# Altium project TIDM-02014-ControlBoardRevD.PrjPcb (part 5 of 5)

## Sheet LDC.SchDoc: Resolver Analog Front-End
size 431 x 279 mm; Date: Not shown in title block; ApprovedBy: Not shown in title block; CheckedBy: Not shown in title block; Author: Not shown in title block; CompanyName: Not shown in title block; DrawnBy: Panacek; Engineer: Not shown in title block; Organization: Not shown in title block; Address1: Not shown in title block; Address2: Not shown in title block; Address3: Not shown in title block; Address4: Not shown in title block; DocumentNumber: 19; Revision: Use project parameter SCH_Rev; SheetNumber: 19; SheetTotal: 19; PageSetup: Record=PageOptions¦CenterHorizontal=True¦CenterVertical=True¦PrintScale=1.00¦XCorrection=1.00¦YCorrection=1.00¦PrintKind=0¦BorderSize=5000000¦LeftOffset=0¦BottomOffset=0¦Orientation=2¦PaperLength=1000¦PaperWidth=1000¦Scale=100¦PaperSource=15¦PrintQuality=600¦MediaType=1¦DitherType=10¦PaperKind=Letter¦PrintScaleMode=1
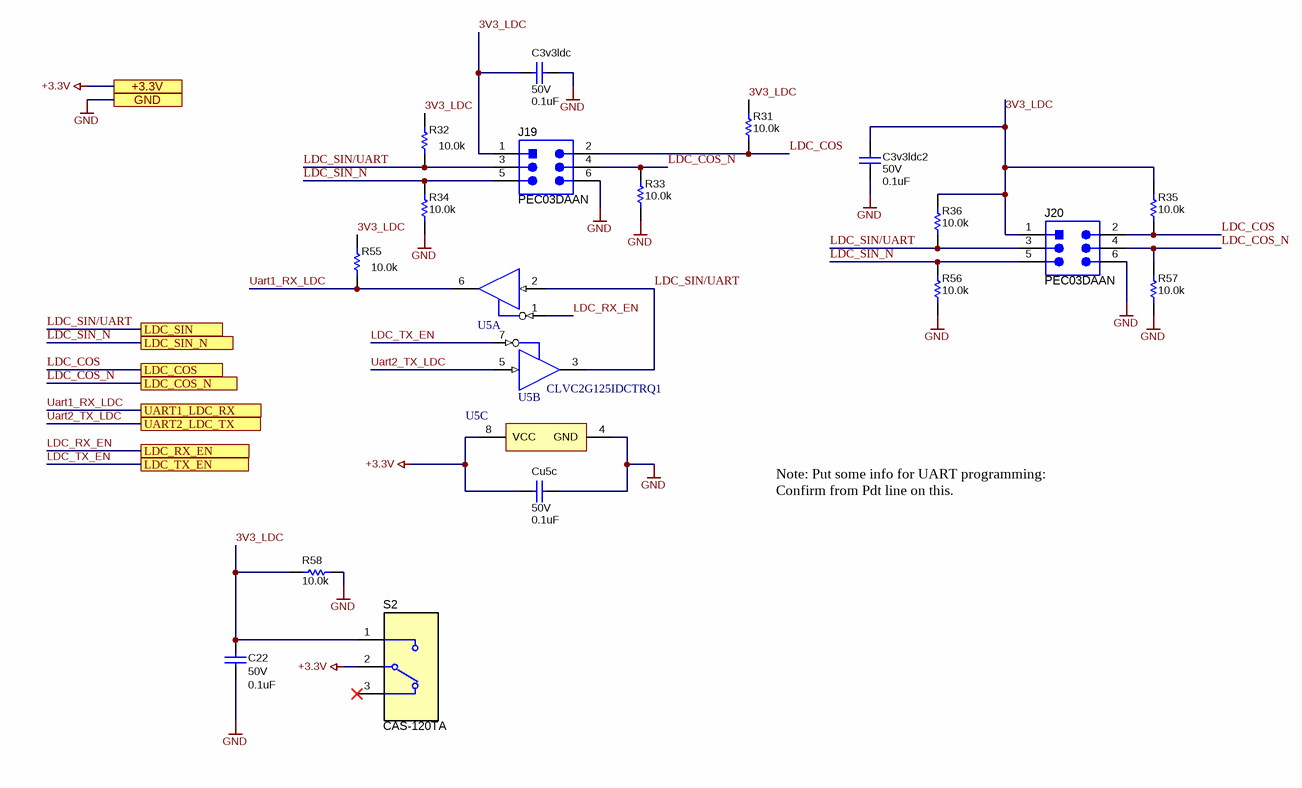
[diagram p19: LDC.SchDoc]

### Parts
C3v3ldc  VDC_V: 50V  ValueDisplayed: 0.1uF  [0603]  (hidden comment: CGA3E2X7R1H104K080AA)
C3v3ldc2  VDC_V: 50V  ValueDisplayed: 0.1uF  [0603]  (hidden comment: CGA3E2X7R1H104K080AA)
C22  VDC_V: 50V  ValueDisplayed: 0.1uF  [0603]  (hidden comment: CGA3E2X7R1H104K080AA)
Cu5c  VDC_V: 50V  ValueDisplayed: 0.1uF  [0603]  (hidden comment: CGA3E2X7R1H104K080AA)
J19  PEC03DAAN  [SULLINS_PEC03DAAN]
J20  PEC03DAAN  [SULLINS_PEC03DAAN]
R31  ValueDisplayed: 10.0k  [0603]  (hidden comment: CRCW060310K0FKEA)
R32  ValueDisplayed: 10.0k  [0603]  (hidden comment: CRCW060310K0FKEA)
R33  ValueDisplayed: 10.0k  [0603]  (hidden comment: CRCW060310K0FKEA)
R34  ValueDisplayed: 10.0k  [0603]  (hidden comment: CRCW060310K0FKEA)
R35  ValueDisplayed: 10.0k  [0603]  (hidden comment: CRCW060310K0FKEA)
R36  ValueDisplayed: 10.0k  [0603]  (hidden comment: CRCW060310K0FKEA)
R55  ValueDisplayed: 10.0k  [0603]  (hidden comment: CRCW060310K0FKEA)
R56  ValueDisplayed: 10.0k  [0603]  (hidden comment: CRCW060310K0FKEA)
R57  ValueDisplayed: 10.0k  [0603]  (hidden comment: CRCW060310K0FKEA)
R58  ValueDisplayed: 10.0k  [0603]  (hidden comment: CRCW060310K0FKEA)
S2  CAS-120TA  [SW_CAS-120TA]
U5  CLVC2G125IDCTRQ1  [DCT0008A_N]  (value not drawn)  (parts A,B,C of 3)

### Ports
+3.3V, GND, LDC_COS, LDC_COS_N, LDC_RX_EN, LDC_SIN, LDC_SIN_N, LDC_TX_EN, UART1_LDC_RX, UART2_LDC_TX

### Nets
+3.3V: Cu5c.1 S2.2 U5.8(VCC) ; port +3.3V
GND: C3v3ldc.2 C3v3ldc2.2 C22.2 Cu5c.2 J19.6 J20.6 R33.1 R34.1 R56.1 R57.1 R58.1 U5.4(GND) ; port GND
3V3_LDC: C3v3ldc.1 C3v3ldc2.1 C22.1 J19.1 J20.1 R31.2 R32.2 R35.2 R36.2 R55.2 R58.2 S2.1  [project net 3V3_LDC_19]
LDC_COS: J19.2 J20.2 R31.1 R35.1 ; port LDC_COS
LDC_COS_N: J19.4 J20.4 R33.2 R57.2 ; port LDC_COS_N
LDC_RX_EN: U5.1(1~{OE}) ; port LDC_RX_EN
LDC_SIN/UART: J19.3 J20.3 R32.1 R36.1 U5.2(1A) U5.3(2Y) ; port LDC_SIN  [project net LDC_SIN]
LDC_SIN_N: J19.5 J20.5 R34.2 R56.2 ; port LDC_SIN_N
LDC_TX_EN: U5.7(2~{OE}) ; port LDC_TX_EN
Uart1_RX_LDC: R55.1 U5.6(1Y) ; port UART1_LDC_RX  [project net UART1_LDC_RX]
Uart2_TX_LDC: U5.5(2A) ; port UART2_LDC_TX  [project net UART2_LDC_TX]

Not connected (* = marked no-connect by the designer): S2 3*

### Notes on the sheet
- Note: Put some info for UART programming: Confirm from Pdt line on this.

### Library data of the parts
C3v3ldc C3v3ldc2 C22 Cu5c = CMP-0007078-4: CAP, CERM, 0.1 uF, 50 V, +/- 10%, X7R, AEC-Q200 Grade 1, 0603; Manufacturer: TDK; TaMin_C: -55°C; ESR_ohm: 29.6m; Polarized: N; SizeAreaWB_mm2: 4.68; Value1: 0.0296 ohm; U/M: EA; Value: 0.1uF; TaMax_C: 125°C; SizeZ_mm: 1; SizeX_mm: 1.6; SizeY_mm: 0.8; SizeArea_mm2: 1.28; AEC Qualified: Y; Cap_F: 100nF; IRMS_A: 971.99mA; AEC Category: Q200
J19 J20 = CMP-0054552-2: Header, 100mil, 3x2, Tin, TH; Manufacturer: Sullins Connector Solutions; Current_A: 3A; Green_Lifecycle: Not Set; Shrouded: N; Gender: Male; Green_REACh: Incomplete; Voltage_V: 1.8kV; Row_Count: 2; RowSpacing_mm: 2.54; Cert_UL: Y
R31-R36 R55-R58 = CMP-0021998-4: RES, 10.0 k, 1%, 0.1 W, AEC-Q200 Grade 0, 0603; Manufacturer: Vishay-Dale; Power_W: 100mW; TempCo: 100 ppm/C; Value_Code: 10k0; Value: 10.0k; EIA_Code: E96; Res_ohm: 10k; SizeX_mm: 1.6; SizeY_mm: 0.8; SizeZ_mm: 1; Value2: 0.1W; SizeArea_mm2: 1.28; AEC Qualified: Y; VDC_V: 75V; AEC Category: Q200; AEC Grade: 0
S2 = CMP-0002139-2: Switch, Slide, SPDT  100mA, SMT; Manufacturer: Copal Electronics; CurrentRating_mA: 100A; SwitchFunction: On-On; VDC_V: 6V; PositionCount: 1
U5 = CMP-0051817-1: Automotive Catalog Dual Bus Buffer Gate with 3-State Outputs, DCT0008A, LARGE T&R; Generic Part Number: SN74LVC2G125-Q1; Manufacturer: Texas Instruments; Logic: True; ICC @ Nom Voltage(Max)(mA): 0.01; F @ Nom Voltage(Max)(Mhz): 150; Input Type: CMOS/TTL; Bits(#): 2; Technology Family: LVC; 3-State Output: Yes; Sub-Family: Non-Inverting Buffer/Driver; Output Drive (IOL/IOH)(Max)(mA): 32/-32; Voltage(Nom)(V): 1.8,2.5,3.3,5; tpd @ Nom Voltage(Max)(ns): 9.1,4.8,4.3,3.7; VCC(Max)(V): 5.5; VCC(Min)(V): 1.65; Schmitt Trigger: No; Output Type: CMOS

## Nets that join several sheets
3V3_L_SMCU_IN: TIDM_02014-ControlBoardRevD-hieararchy (R115.2), Safety MCU (C19.1 C20.1 J22.20 J22.22)
24V_L_SMCU_IN: TIDM_02014-ControlBoardRevD-hieararchy (R113.2), Safety MCU (C17.1 C18.1 J22.19 J22.21)
+3.3V: TIDM_02014-ControlBoardRevD-hieararchy (R104.1), power_ls (R324.1), can_lin_interface (8 pins), thermal-management (7 pins), eqep_ecap_interface (C1300.1 R1303.1 U1300.2), controlSOM_Subsystem (10 pins), Safety MCU (C21.1 U1.5 U1.6), Safe State Behavior Settings (7 pins), resolver (6 pins), LDC (Cu5c.1 S2.2 U5.8)
+3.3V_C-V: TIDM_02014-ControlBoardRevD-hieararchy (R103.1 R104.2), power_ls (R325.1), Current Sense Connector (6 pins), voltage-sensing (C804.1 C805.1 R800.2 U801.14), Voltage-sense-LVside (C9.1 U3.5), U_current-sensing-lem/Phase A (C10_Phase_A.1 R19_Phase_A.2 U4_Phase_A.5), U_current-sensing-lem/Phase C (C10_Phase_C.1 R19_Phase_C.2 U4_Phase_C.5), U_current-sensing-lem/Phase B (C10_Phase_B.1 R19_Phase_B.2 U4_Phase_B.5)
+3.3V_H: power_hs (C216.1 C217.1 U201.5), gd-interface (7 pins)
+3.3V_L: TIDM_02014-ControlBoardRevD-hieararchy (R116.2), power_ls (C308.1 C309.1 U300.5)
+3.3V_L_SF: TIDM_02014-ControlBoardRevD-hieararchy (R115.1 R116.1), gd-interface (13 pins)
+5V: TIDM_02014-ControlBoardRevD-hieararchy (R106.1), power_ls (13 pins), can_lin_interface (6 pins), thermal-management (C903.1 U901.1), eqep_ecap_interface (10 pins), controlSOM_Subsystem (10 pins), voltage-sensing (C810.2 FB801.2)
+5V_CAN_WU: TIDM_02014-ControlBoardRevD-hieararchy (R105.2 R106.2), can_lin_interface (C602.2 U601.3)
+5V_ISO: TIDM_02014-ControlBoardRevD-hieararchy (J102.9), can_lin_interface (7 pins)
+12V_H: TIDM_02014-ControlBoardRevD-hieararchy (J109.1 J110.1), power_hs (20 pins), thermal-management (D900.1)
+12V_L: power_ls (25 pins), can_lin_interface (C611.2 R619.2 U601.10)
+15V: power_lem (12 pins), Current Sense Connector (J7.1 J8.1 J9.1), resolver (15 pins)
+24V_H: power_hs (9 pins), gd-interface (J1000.37 J1001.37 J1002.37)
+24V_L: TIDM_02014-ControlBoardRevD-hieararchy (R114.2), power_ls (Rjump12v.1 Rjumppre.1)
+24V_L_SF: TIDM_02014-ControlBoardRevD-hieararchy (R113.1 R114.1), gd-interface (J1000.39 J1001.39 J1002.39)
-15V: power_lem (10 pins), Current Sense Connector (J7.3 J8.3 J9.3)
GND: TIDM_02014-ControlBoardRevD-hieararchy (10 pins), power_hs (40 pins), power_ls (63 pins), power_lem (48 pins), can_lin_interface (16 pins), thermal-management (16 pins), eqep_ecap_interface (12 pins), Current Sense Connector (10 pins), gd-interface (42 pins), controlSOM_Subsystem (51 pins), Safety MCU (8 pins), Safe State Behavior Settings (13 pins), voltage-sensing (8 pins), Voltage-sense-LVside (16 pins), U_current-sensing-lem/Phase A (13 pins), U_current-sensing-lem/Phase C (13 pins), U_current-sensing-lem/Phase B (13 pins), resolver (98 pins), LDC (12 pins)
GND_ISO: TIDM_02014-ControlBoardRevD-hieararchy (C101.2 J102.3 J102.5 R101.1), can_lin_interface (11 pins)
HV: TIDM_02014-ControlBoardRevD-hieararchy (J107.1 J108.1), Safety MCU (J5.1 J5.2), voltage-sensing (U801.1)
Pgndin: TIDM_02014-ControlBoardRevD-hieararchy (J107.3 J108.3), Safety MCU (J10.1 J10.2), voltage-sensing (12 pins)
VIN_12V: TIDM_02014-ControlBoardRevD-hieararchy (D100.1 S100.1 S101.1), power_hs (7 pins), power_ls (7 pins), power_lem (7 pins)
VREF: controlSOM_Subsystem (C7.1 J15.83 J15.85 U2.5), Voltage-sense-LVside (R25.1)
VREF_1/2: controlSOM_Subsystem (C4.1 U2.1), resolver (R516.1 R529.1 R548.1)
AD_H_A: gd-interface (J1000.16), controlSOM_Subsystem (J16.52), Safety MCU (J22.9), Safe State Behavior Settings (R43.2)
AD_H_B: gd-interface (J1001.16), controlSOM_Subsystem (J16.56), Safe State Behavior Settings (R44.2)
AD_H_C: gd-interface (J1002.16), controlSOM_Subsystem (J16.60), Safe State Behavior Settings (R45.2)
AD_L_A: gd-interface (J1000.15), controlSOM_Subsystem (J16.50), Safety MCU (J22.11), Safe State Behavior Settings (R46.2)
AD_L_B: gd-interface (J1001.15), controlSOM_Subsystem (J16.54), Safe State Behavior Settings (R47.2)
AD_L_C: gd-interface (J1002.15), controlSOM_Subsystem (J16.58), Safe State Behavior Settings (R48.2)
Alert_A: Current Sense Connector (J6.5 U7.1), controlSOM_Subsystem (J15.2)
Alert_B: Current Sense Connector (J6.6 U7.3), controlSOM_Subsystem (J15.74)
Alert_C: Current Sense Connector (J6.7 U7.6), controlSOM_Subsystem (J15.70)
Alert_tmcs: Current Sense Connector (TP_alert.1 U7.4), controlSOM_Subsystem (J14.114)
AMBIENT_TEMP: thermal-management (C904.1 R900.2), controlSOM_Subsystem (J15.96)
CAN_H: TIDM_02014-ControlBoardRevD-hieararchy (J103.7), can_lin_interface (L600.2 R600.2 R602.2 U604.2)
CAN_INH: can_lin_interface (R616.1), controlSOM_Subsystem (J15.30)
CAN_L: TIDM_02014-ControlBoardRevD-hieararchy (J103.2), can_lin_interface (L600.1 R605.1 R608.2 U604.1)
CLKIN/OUTP/OUT: voltage-sensing (U801.11), Voltage-sense-LVside (C6n.2 R6.1 R9.1 R11.1)
COS+: TIDM_02014-ControlBoardRevD-hieararchy (J101.8), resolver (R545.2)
COS-: TIDM_02014-ControlBoardRevD-hieararchy (J101.4), resolver (R538.2)
DOUT/OUTN/REFIN: voltage-sensing (U801.10), Voltage-sense-LVside (R2.1 R12.1 R25.2)
EXC+: TIDM_02014-ControlBoardRevD-hieararchy (J101.7), resolver (R503.2)
EXC-: TIDM_02014-ControlBoardRevD-hieararchy (J101.3), resolver (R504.2)
EXC_OC_OT: controlSOM_Subsystem (J15.52), resolver (R551.1)
FAN-CTRL: TIDM_02014-ControlBoardRevD-hieararchy (J109.2 J110.2), thermal-management (D900.2 Q900.3)
FAN_PWM: thermal-management (R906.1), controlSOM_Subsystem (J15.4)
FLT_AMCsupply5V: controlSOM_Subsystem (J16.46), voltage-sensing (R800.1 U800.1)
FLT_CANSupply: can_lin_interface (R620.1 U602.1), controlSOM_Subsystem (J14.105)
FSITX_CLK: eqep_ecap_interface (S1300.3), controlSOM_Subsystem (J11.7 J15.49)
FSITX_D0: eqep_ecap_interface (S1300.1), controlSOM_Subsystem (J11.9 J15.53)
FSITX_D1: eqep_ecap_interface (S1300.2), controlSOM_Subsystem (J11.12 J15.51)
GDAH: gd-interface (J1000.24 J1000.26 R1013.2), controlSOM_Subsystem (J15.16)
GDAL: gd-interface (J1000.21 J1000.23 R1013.1), controlSOM_Subsystem (J15.14)
GDBH: gd-interface (J1001.24 J1001.26 R1014.2), controlSOM_Subsystem (J15.12)
GDBL: gd-interface (J1001.21 J1001.23 R1014.1), controlSOM_Subsystem (J15.10)
GDCH: gd-interface (J1002.24 J1002.26 R1012.2), controlSOM_Subsystem (J15.8)
GDCL: gd-interface (J1002.21 J1002.23 R1012.1), controlSOM_Subsystem (J15.6)
IFB_I2C_SCL: Current Sense Connector (J6.3), controlSOM_Subsystem (J15.61)
IFB_I2C_SDA: Current Sense Connector (J6.2), controlSOM_Subsystem (J15.63)
IFB_U: controlSOM_Subsystem (J15.104), U_current-sensing-lem/Phase A (C13_Phase_A.1 R20_Phase_A.2)
IFB_U_N: controlSOM_Subsystem (J15.118), U_current-sensing-lem/Phase A (R1_Phase_A.1)
IFB_U_P: controlSOM_Subsystem (J15.120), U_current-sensing-lem/Phase A (R3_Phase_A.1)
IFB_V: controlSOM_Subsystem (J15.91), U_current-sensing-lem/Phase C (C13_Phase_C.1 R20_Phase_C.2)
IFB_V_N: controlSOM_Subsystem (J15.114), U_current-sensing-lem/Phase C (R1_Phase_C.1)
IFB_V_P: controlSOM_Subsystem (J15.116), U_current-sensing-lem/Phase C (R3_Phase_C.1)
IFB_VOC_U: Current Sense Connector (J6.8 U8.1), controlSOM_Subsystem (J15.31)
IFB_VOC_V: Current Sense Connector (J6.10 U8.6), controlSOM_Subsystem (J14.106 J15.35)
IFB_VOC_W: Current Sense Connector (J6.9 U8.3), controlSOM_Subsystem (J14.108 J15.33)
IFB_W: controlSOM_Subsystem (J15.102 J15.108), U_current-sensing-lem/Phase B (C13_Phase_B.1 R20_Phase_B.2)
IFB_W_N: controlSOM_Subsystem (J15.105 J15.113), U_current-sensing-lem/Phase B (R1_Phase_B.1)
IFB_W_P: controlSOM_Subsystem (J15.107 J15.115), U_current-sensing-lem/Phase B (R3_Phase_B.1)
ILEM_A: Current Sense Connector (J7.2), U_current-sensing-lem/Phase A (R21_Phase_A.1 R23_Phase_A.2)
ILEM_B: Current Sense Connector (J8.2), U_current-sensing-lem/Phase C (R21_Phase_C.1 R23_Phase_C.2)
ILEM_B: Current Sense Connector (J9.2), U_current-sensing-lem/Phase B (R21_Phase_B.1 R23_Phase_B.2)
ISOCAN_H: TIDM_02014-ControlBoardRevD-hieararchy (J102.7), can_lin_interface (L601.3 R601.2 R603.2 U605.2)
ISOCAN_L: TIDM_02014-ControlBoardRevD-hieararchy (J102.2), can_lin_interface (L601.4 R607.1 R610.2 U605.1)
LDC_COS: controlSOM_Subsystem (J15.103 Rjldc2.2), LDC (J19.2 J20.2 R31.1 R35.1)
LDC_COS_N: controlSOM_Subsystem (J15.101 Rjldc1.2), LDC (J19.4 J20.4 R33.2 R57.2)
LDC_RX_EN: controlSOM_Subsystem (J14.120), LDC (U5.1)
LDC_SIN: controlSOM_Subsystem (J15.112), LDC (6 pins)
LDC_SIN_N: controlSOM_Subsystem (J15.110), LDC (J19.5 J20.5 R34.2 R56.2)
LDC_TX_EN: controlSOM_Subsystem (J14.118), LDC (U5.7)
LIN: TIDM_02014-ControlBoardRevD-hieararchy (J103.8), can_lin_interface (C610.1 D600.1 J600.2 U603.6)
LINA_RX: can_lin_interface (R614.1), controlSOM_Subsystem (R28.2)
LINA_TX: can_lin_interface (R615.1), controlSOM_Subsystem (R29.2)
LVSS_EN: gd-interface (J1000.28 J1001.28 J1002.28), controlSOM_Subsystem (J15.48), Safety MCU (J22.17 U1.3), Safe State Behavior Settings (R4.1 R5.2)
LVSS_IN_HS_A: gd-interface (J1000.30 R1017.1), controlSOM_Subsystem (J14.115), Safety MCU (J22.13), Safe State Behavior Settings (R37.1 R49.2)
LVSS_IN_HS_B: gd-interface (J1001.30 R1017.2 R1018.1), controlSOM_Subsystem (J14.111), Safe State Behavior Settings (R38.1 R50.2)
LVSS_IN_HS_C: gd-interface (J1002.30 R1018.2), controlSOM_Subsystem (J14.87), Safe State Behavior Settings (R39.1 R51.2)
LVSS_IN_LS_A: gd-interface (J1000.17 R1015.1), controlSOM_Subsystem (J14.113), Safety MCU (J22.15), Safe State Behavior Settings (R40.1 R52.2)
LVSS_IN_LS_B: gd-interface (J1001.17 R1015.2 R1016.1), controlSOM_Subsystem (J14.109), Safe State Behavior Settings (R41.1 R53.2)
LVSS_IN_LS_C: gd-interface (J1002.17 R1016.2), controlSOM_Subsystem (J14.100), Safe State Behavior Settings (R42.1 R54.2)
MCAN_RX: can_lin_interface (TP603.1 U600.3), controlSOM_Subsystem (J15.38)
MCAN_TX: can_lin_interface (TP601.1 U600.2), controlSOM_Subsystem (J15.36)
MCU_QEP_A: eqep_ecap_interface (U1300.5), controlSOM_Subsystem (J15.71)
MCU_QEP_B: eqep_ecap_interface (U1300.6), controlSOM_Subsystem (J15.69)
MCU_QEP_I: eqep_ecap_interface (U1300.7), controlSOM_Subsystem (J15.65)
MOTOR_TEMP: thermal-management (C908.1 R904.1 TP900.1), controlSOM_Subsystem (J15.99)
nFLT1_H: gd-interface (J1000.20 J1001.20 J1002.20 R1027.2), controlSOM_Subsystem (J15.55), Safety MCU (J22.1)
nFLT1_L: gd-interface (J1000.29 J1001.29 J1002.29 R1030.2), controlSOM_Subsystem (J15.37), Safety MCU (J22.3)
nFLT2_H: gd-interface (J1000.18 R1019.1 R1034.2 R1036.2), controlSOM_Subsystem (J15.57), Safety MCU (J22.5)
nFLT2_H2: gd-interface (J1001.18 R1020.1 R1034.1), controlSOM_Subsystem (J16.55)
nFLT2_H3: gd-interface (J1002.18 R1021.1 R1036.1), controlSOM_Subsystem (J16.59)
nFLT2_L: gd-interface (J1000.31 R1022.2 R1040.2 R1042.2), controlSOM_Subsystem (J15.59), Safety MCU (J22.7)
nFLT2_L2: gd-interface (J1001.31 R1023.2 R1040.1), controlSOM_Subsystem (J16.53)
nFLT2_L3: gd-interface (J1002.31 R1024.2 R1042.1), controlSOM_Subsystem (J16.57)
NTC+: TIDM_02014-ControlBoardRevD-hieararchy (J101.6), thermal-management (C902.1 U900.4)
NTC-: TIDM_02014-ControlBoardRevD-hieararchy (J101.1), thermal-management (C907.1 R902.2 R903.2)
PMIC_3V3_OUT: TIDM_02014-ControlBoardRevD-hieararchy (R103.2), controlSOM_Subsystem (J15.28)
PMIC_5V0_OUT: TIDM_02014-ControlBoardRevD-hieararchy (R105.1), controlSOM_Subsystem (J15.34)
PMIC_SAFE_OUT1: controlSOM_Subsystem (J15.32), Safety MCU (U1.1)
Power_EN_HS: gd-interface (J1000.36 J1001.36 J1002.36), controlSOM_Subsystem (J15.23)
Power_EN_LoadSW: power_hs (R237.1 R241.2 U202.7), power_ls (R302.1 R306.2 U301.7), power_lem (R405.1 R417.2 U401.7)
Power_EN_LS: gd-interface (J1000.33 J1001.33 J1002.33), controlSOM_Subsystem (J15.25)
Power_good: gd-interface (U1000.4), controlSOM_Subsystem (J15.50)
PWM1_H: gd-interface (J1000.14), controlSOM_Subsystem (J15.15 TP1.1)
PWM1_L: gd-interface (J1000.12), controlSOM_Subsystem (J15.13 TP2.1)
PWM2_H: gd-interface (J1001.14), controlSOM_Subsystem (J15.11 TP3.1)
PWM2_L: gd-interface (J1001.12), controlSOM_Subsystem (J15.9 TP4.1)
PWM3_H: gd-interface (J1002.14), controlSOM_Subsystem (J15.7 TP5.1)
PWM3_L: gd-interface (J1002.12), controlSOM_Subsystem (J15.5 TP6.1)
RES2_COS: controlSOM_Subsystem (J16.119), resolver (C522.1 C524.2 R555.1 R557.2)
RES2_COS_N: controlSOM_Subsystem (J16.117), resolver (C524.1 C525.2 R557.1 R559.2)
RES2_SIN: controlSOM_Subsystem (J16.115), resolver (C521.1 C523.2 R554.1 R556.2)
RES2_SIN_N: controlSOM_Subsystem (J16.113), resolver (C523.1 C526.2 R556.1 R558.2)
RES_COS: controlSOM_Subsystem (J16.116), Safety MCU (J22.10), resolver (C519.2 C530.2 R547.2 R568.2)
RES_COS_N: controlSOM_Subsystem (J16.114), resolver (C530.1 R568.1 R569.2)
RES_EXC: controlSOM_Subsystem (J15.97), Safety MCU (J22.12), resolver (R513.1)
RES_EXC_OUT_PWM: controlSOM_Subsystem (S1.5), resolver (R550.1)
RES_SIN: controlSOM_Subsystem (J16.120), Safety MCU (J22.8), resolver (C512.2 C527.2 R528.2 R563.2)
RES_SIN_N: controlSOM_Subsystem (J16.118), resolver (C527.1 R563.1 R564.2)
RX: can_lin_interface (R609.1 TP604.1), controlSOM_Subsystem (J16.23)
Safety_OR_gate_out: controlSOM_Subsystem (J15.72), Safety MCU (J22.14 U1.4)
SIN+: TIDM_02014-ControlBoardRevD-hieararchy (J101.9), resolver (R526.2)
SIN-: TIDM_02014-ControlBoardRevD-hieararchy (J101.5), resolver (R521.2)
TX: can_lin_interface (R604.1 TP600.1), controlSOM_Subsystem (J16.21)
U_N: Current Sense Connector (J6.14), U_current-sensing-lem/Phase A (C1_Phase_A.1 C8_Phase_A.2 R1_Phase_A.2)
U_P: Current Sense Connector (J6.13), U_current-sensing-lem/Phase A (C1_Phase_A.2 C14_Phase_A.2 R3_Phase_A.2)
UART1_LDC_RX: controlSOM_Subsystem (R27.2), LDC (R55.1 U5.6)
UART2_LDC_TX: controlSOM_Subsystem (R30.2), LDC (U5.5)
UCC5890_CLK: gd-interface (J1000.10 J1001.10 J1002.10), controlSOM_Subsystem (J16.34 TP9.1)
UCC5890_nCS: gd-interface (6 pins), controlSOM_Subsystem (J16.36 TP10.1)
UCC5890_SDI: gd-interface (J1000.5 J1001.5 J1002.5), controlSOM_Subsystem (J16.30 TP7.1)
UCC5890_SDO: gd-interface (J1000.8 J1001.8 J1002.8), controlSOM_Subsystem (J16.32 TP8.1)
V_N: Current Sense Connector (J6.17), U_current-sensing-lem/Phase C (C1_Phase_C.1 C8_Phase_C.2 R1_Phase_C.2)
V_P: Current Sense Connector (J6.16), U_current-sensing-lem/Phase C (C1_Phase_C.2 C14_Phase_C.2 R3_Phase_C.2)
VDC: controlSOM_Subsystem (J15.93), Safety MCU (J22.6), voltage-sensing (R804.2)
Vdc_C: controlSOM_Subsystem (J14.102 J15.3 J15.54), Safety MCU (J22.2), Voltage-sense-LVside (R11.2)
Vdc_D: controlSOM_Subsystem (J14.104 J15.56), Safety MCU (J22.4), Voltage-sense-LVside (J1.1 R13.2)
VDC_diff_2: voltage-sensing (R804.1), Voltage-sense-LVside (C16.1 R10.2)
VDC_N: controlSOM_Subsystem (J15.111), Voltage-sense-LVside (C3.1 C3d1.2 R2.2)
VDC_P: controlSOM_Subsystem (J15.109), Voltage-sense-LVside (C3.2 C3d2.2 R6.2)
Voc_tmcs: Current Sense Connector (TP_voc.1 U8.4), controlSOM_Subsystem (J14.112)
VOUT_C_N: Current Sense Connector (J6.20), U_current-sensing-lem/Phase B (C1_Phase_B.1 C8_Phase_B.2 R1_Phase_B.2)
VOUT_C_P: Current Sense Connector (J6.19), U_current-sensing-lem/Phase B (C1_Phase_B.2 C14_Phase_B.2 R3_Phase_B.2)

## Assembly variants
001: not fitted C3d1 C3d2 C5 C16 C100 C101 C102 C507 C511 C513 C520 C521 C522 C525 C526 C527 C530 C810 R2 R6 R9 R10 R25 R100 R101 R102 R103 R104 R105 R302 R306 R405 R417 R541 R562 R563 R566 R568 R600 R601 R608 R610 R907 R1304 Rjump12v TP100 TP500 TP501 TP502 TP503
